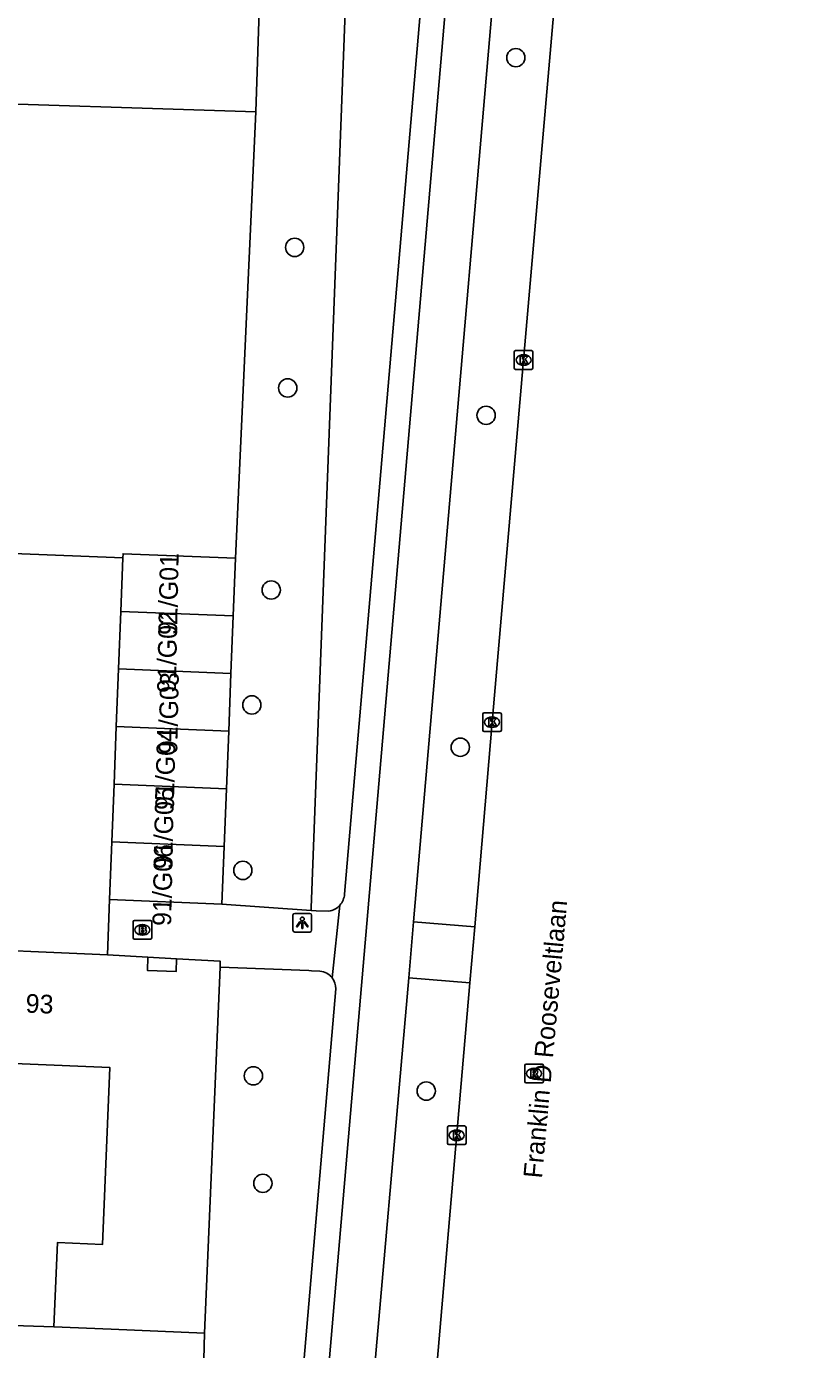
# Model space of a CAD drawing. Extents: x 160787 to 161428, y 386828 to 387483.
# Drawn here: x 161365.7 to 161407.5, y 386925.5 to 386996.4 of the extents above; entities that cross this region are included whole.
import ezdxf

# ---------------------------------------------------------------- set-up
doc = ezdxf.new("R2010")
doc.units = 0
for name, color, linetype in [('IMGEO_Boom', 7, 'Continuous'), ('IMGEO_Brandkraan', 7, 'Continuous'), ('IMGEO_Fietspad_gesloten', 7, 'Continuous'), ('IMGEO_Groenvoorziening', 7, 'Continuous'), ('IMGEO_Kolk', 7, 'Continuous'), ('IMGEO_Lichtpunt', 7, 'Continuous'), ('IMGEO_Openbare_ruimte_label', 7, 'Continuous'), ('IMGEO_Pand', 7, 'Continuous'), ('IMGEO_Pand_nummerreeks', 7, 'Continuous'), ('IMGEO_Rijbaan_lokaal_gesloten', 7, 'Continuous'), ('IMGEO_Rijbaan_lokaal_open', 7, 'Continuous'), ('IMGEO_Rioolput', 7, 'Continuous'), ('IMGEO_Voetpad_open', 7, 'Continuous')]:
    doc.layers.add(name, color=color, linetype=linetype)

msp = doc.modelspace()

# ---------------------------------------------------------------- linework, layer by layer
at = {"layer": 'IMGEO_Boom'}
for centre in [(161391.916, 386994.712), (161380.077, 386984.552), (161379.703, 386977.028), (161390.324, 386975.563), (161378.819, 386966.209), (161377.782, 386960.057), (161388.941, 386957.792), (161377.301, 386951.199), (161377.865, 386940.199), (161387.118, 386939.384), (161378.372, 386934.443)]:
    msp.add_circle(centre, 0.489, dxfattribs=at)
at = {"layer": 'IMGEO_Brandkraan'}
for p, q in [((161371.496, 386948.514), (161372.348, 386948.514)), ((161371.421, 386947.588), (161371.421, 386948.44)), ((161371.909, 386948.294), (161371.934, 386948.294)), ((161372.422, 386948.44), (161372.422, 386947.588)), ((161372.348, 386947.514), (161371.496, 386947.514)), ((161371.932, 386947.734), (161371.907, 386947.734))]:
    msp.add_line(p, q, dxfattribs=at)
for points in [[(161371.496, 386948.514), (161372.348, 386948.514)], [(161371.421, 386947.588), (161371.421, 386948.44)], [(161371.769, 386948.214), (161371.769, 386947.814), (161371.982, 386947.814)], [(161372, 386948.214), (161371.769, 386948.214)], [(161371.948, 386948.133), (161371.894, 386948.133), (161371.894, 386948.057)], [(161371.894, 386948.057), (161371.947, 386948.057)], [(161371.956, 386947.981), (161371.894, 386947.981), (161371.894, 386947.9)], [(161371.894, 386947.9), (161371.956, 386947.9)], [(161372.422, 386948.44), (161372.422, 386947.588)], [(161372.348, 386947.514), (161371.496, 386947.514)]]:
    msp.add_lwpolyline(points, dxfattribs=at)
for centre, radius, start, end in [((161371.498, 386948.438), 0.0765, 91.55205, 178.44795), ((161371.498, 386948.438), 0.0765, 91.55205, 178.44795), ((161372.346, 386948.438), 0.0765, 1.55205, 88.44795), ((161372.346, 386948.438), 0.0765, 1.55205, 88.44795), ((161371.949, 386948.095), 0.0379, 267.82845, 90.93552), ((161371.957, 386947.94), 0.0404, 269.87594, 90.50774), ((161371.988, 386948.065), 0.251, 268.66757, 293.53466), ((161372.004, 386948.069), 0.145, 59.4692, 91.53667), ((161372.029, 386948.116), 0.0922, 285.51372, 58.15012), ((161372.034, 386947.924), 0.105, 301.31148, 78.98903), ((161371.498, 386947.59), 0.0765, 181.55205, 268.44795), ((161371.498, 386947.59), 0.0765, 181.55205, 268.44795), ((161372.346, 386947.59), 0.0765, 271.55205, 358.44795), ((161372.346, 386947.59), 0.0765, 271.55205, 358.44795)]:
    msp.add_arc(centre, radius, start, end, dxfattribs=at)
for centre, major_axis, ratio, start_param, end_param in [((161371.908, 386948.014), (-0.387, 0.002), 0.722429, 4.712389, 7.853982), ((161371.933, 386948.014), (-0.39, 0.002), 0.717154, 1.570796, 4.712389)]:
    msp.add_ellipse(centre, major_axis=major_axis, ratio=ratio, start_param=start_param, end_param=end_param, dxfattribs=at)
at = {"layer": 'IMGEO_Fietspad_gesloten'}
for points in [[(161407.533, 387249.962), (161407.461, 387247.985), (161406.867, 387233.118), (161405.924, 387208.411), (161404.815, 387191.258), (161403.255, 387173.245), (161393.155, 387056.153), (161390.436, 387023.76), (161389.845, 387017.132), (161384.142, 386950.642), (161379.486, 386896.649), (161376.409, 386860.953), (161376.305, 386860.089), (161375.969, 386856.03)], [(161386.443, 386948.447), (161392.377, 387017.448)], [(161386.193, 386945.455), (161386.443, 386948.447)], [(161380.021, 386874.137), (161380.151, 386878.097), (161380.414, 386880.385), (161381.868, 386896.26), (161386.193, 386945.455)]]:
    msp.add_lwpolyline(points, dxfattribs=at)
at = {"layer": 'IMGEO_Groenvoorziening'}
for points in [[(161383.565, 387017.876), (161382.888, 387000), (161380.963, 386949.203), (161380.958, 386949.059)], [(161378.212, 386998.287), (161377.988, 386991.819)], [(161377.988, 386991.819), (161324.809, 386993.526)], [(161376.903, 386967.918), (161377.988, 386991.819)], [(161360.13, 386926.991), (161367.184, 386926.77)], [(161375.253, 386926.43), (161375.065, 386919.394)]]:
    msp.add_lwpolyline(points, dxfattribs=at)
at = {"layer": 'IMGEO_Kolk'}
for p, q in [((161391.83, 386978.098), (161391.83, 386978.95)), ((161391.905, 386979.024), (161392.757, 386979.024)), ((161392.831, 386978.95), (161392.831, 386978.098)), ((161392.341, 386978.244), (161392.316, 386978.244)), ((161392.318, 386978.804), (161392.343, 386978.804)), ((161392.757, 386978.024), (161391.905, 386978.024)), ((161390.14, 386958.706), (161390.14, 386959.558)), ((161390.215, 386959.632), (161391.067, 386959.632)), ((161390.628, 386959.412), (161390.653, 386959.412)), ((161391.141, 386959.558), (161391.141, 386958.706)), ((161391.067, 386958.632), (161390.215, 386958.632)), ((161390.651, 386958.852), (161390.626, 386958.852)), ((161388.25, 386936.59), (161388.25, 386937.442)), ((161388.325, 386937.516), (161389.177, 386937.516)), ((161388.738, 386937.296), (161388.763, 386937.296)), ((161389.251, 386937.442), (161389.251, 386936.59)), ((161389.177, 386936.516), (161388.325, 386936.516)), ((161388.761, 386936.736), (161388.736, 386936.736))]:
    msp.add_line(p, q, dxfattribs=at)
for points in [[(161391.83, 386978.098), (161391.83, 386978.95)], [(161391.905, 386979.024), (161392.757, 386979.024)], [(161392.831, 386978.95), (161392.831, 386978.098)], [(161392.151, 386978.724), (161392.274, 386978.724), (161392.274, 386978.573), (161392.404, 386978.724), (161392.568, 386978.724), (161392.422, 386978.573), (161392.575, 386978.324), (161392.423, 386978.324), (161392.338, 386978.488), (161392.274, 386978.421), (161392.274, 386978.324), (161392.151, 386978.324), (161392.151, 386978.724)], [(161392.757, 386978.024), (161391.905, 386978.024)], [(161390.14, 386958.706), (161390.14, 386959.558)], [(161390.215, 386959.632), (161391.067, 386959.632)], [(161390.461, 386959.332), (161390.584, 386959.332), (161390.584, 386959.181), (161390.714, 386959.332), (161390.878, 386959.332), (161390.732, 386959.181), (161390.885, 386958.932), (161390.733, 386958.932), (161390.648, 386959.096), (161390.584, 386959.029), (161390.584, 386958.932), (161390.461, 386958.932), (161390.461, 386959.332)], [(161391.141, 386959.558), (161391.141, 386958.706)], [(161391.067, 386958.632), (161390.215, 386958.632)], [(161388.25, 386936.59), (161388.25, 386937.442)], [(161388.325, 386937.516), (161389.177, 386937.516)], [(161388.571, 386937.216), (161388.694, 386937.216), (161388.694, 386937.065), (161388.824, 386937.216), (161388.988, 386937.216), (161388.842, 386937.065), (161388.995, 386936.816), (161388.843, 386936.816), (161388.758, 386936.98), (161388.694, 386936.913), (161388.694, 386936.816), (161388.571, 386936.816), (161388.571, 386937.216)], [(161389.251, 386937.442), (161389.251, 386936.59)], [(161389.177, 386936.516), (161388.325, 386936.516)]]:
    msp.add_lwpolyline(points, dxfattribs=at)
for centre, start, end in [((161391.907, 386978.948), 91.55205, 178.44795), ((161391.907, 386978.948), 91.55205, 178.44795), ((161392.755, 386978.948), 1.55205, 88.44795), ((161392.755, 386978.948), 1.55205, 88.44795), ((161391.907, 386978.1), 181.55205, 268.44795), ((161391.907, 386978.1), 181.55205, 268.44795), ((161392.755, 386978.1), 271.55205, 358.44795), ((161392.755, 386978.1), 271.55205, 358.44795), ((161390.217, 386959.556), 91.55205, 178.44795), ((161390.217, 386959.556), 91.55205, 178.44795), ((161391.065, 386959.556), 1.55205, 88.44795), ((161391.065, 386959.556), 1.55205, 88.44795), ((161390.217, 386958.708), 181.55205, 268.44795), ((161390.217, 386958.708), 181.55205, 268.44795), ((161391.065, 386958.708), 271.55205, 358.44795), ((161391.065, 386958.708), 271.55205, 358.44795), ((161388.327, 386937.44), 91.55205, 178.44795), ((161388.327, 386937.44), 91.55205, 178.44795), ((161389.175, 386937.44), 1.55205, 88.44795), ((161389.175, 386937.44), 1.55205, 88.44795), ((161388.327, 386936.592), 181.55205, 268.44795), ((161388.327, 386936.592), 181.55205, 268.44795), ((161389.175, 386936.592), 271.55205, 358.44795), ((161389.175, 386936.592), 271.55205, 358.44795)]:
    msp.add_arc(centre, 0.0765, start, end, dxfattribs=at)
for centre, major_axis, ratio, start_param, end_param in [((161392.317, 386978.524), (-0.387, 0.002), 0.722429, 4.712389, 7.853982), ((161392.342, 386978.524), (-0.39, 0.002), 0.717154, 1.570796, 4.712389), ((161390.627, 386959.132), (-0.387, 0.002), 0.722429, 4.712389, 7.853982), ((161390.652, 386959.132), (-0.39, 0.002), 0.717154, 1.570796, 4.712389), ((161388.737, 386937.016), (-0.387, 0.002), 0.722429, 4.712389, 7.853982), ((161388.762, 386937.016), (-0.39, 0.002), 0.717154, 1.570796, 4.712389)]:
    msp.add_ellipse(centre, major_axis=major_axis, ratio=ratio, start_param=start_param, end_param=end_param, dxfattribs=at)
at = {"layer": 'IMGEO_Lichtpunt'}
for p, q in [((161379.984, 386948.798), (161379.984, 386947.991)), ((161379.984, 386948.798), (161379.984, 386947.991)), ((161380.886, 386948.893), (161380.078, 386948.893)), ((161380.886, 386948.893), (161380.078, 386948.893)), ((161380.98, 386947.991), (161380.98, 386948.798)), ((161380.98, 386947.991), (161380.98, 386948.798)), ((161380.078, 386947.897), (161380.886, 386947.897)), ((161380.078, 386947.897), (161380.886, 386947.897))]:
    msp.add_line(p, q, dxfattribs=at)
for points in [[(161380.358, 386948.462), (161380.397, 386948.434), (161380.209, 386948.172), (161380.171, 386948.199), (161380.358, 386948.462)], [(161380.46, 386948.414), (161380.507, 386948.414), (161380.507, 386948.092), (161380.46, 386948.092), (161380.46, 386948.414)], [(161380.57, 386948.434), (161380.608, 386948.461), (161380.795, 386948.199), (161380.756, 386948.171), (161380.57, 386948.434)]]:
    msp.add_lwpolyline(points, dxfattribs=at)
msp.add_circle((161380.483, 386948.596), 0.0994, dxfattribs=at)
for centre, start, end in [((161380.078, 386948.798), 90, 180), ((161380.078, 386948.798), 90, 180), ((161380.886, 386948.798), 0, 90), ((161380.886, 386948.798), 0, 90), ((161380.078, 386947.991), 180, 270), ((161380.078, 386947.991), 180, 270), ((161380.886, 386947.991), 270, 0), ((161380.886, 386947.991), 270, 360)]:
    msp.add_arc(centre, 0.0946, start, end, dxfattribs=at)
at = {"layer": 'IMGEO_Pand'}
for points in [[(161370.765, 386965.067), (161370.877, 386967.928)], [(161370.877, 386967.928), (161370.886, 386968.153), (161376.903, 386967.918)], [(161376.903, 386967.918), (161376.782, 386964.832)], [(161370.644, 386961.981), (161370.765, 386965.067)], [(161376.782, 386964.832), (161370.765, 386965.067)], [(161376.782, 386964.832), (161376.661, 386961.745)], [(161370.523, 386958.894), (161370.644, 386961.981)], [(161376.661, 386961.745), (161370.644, 386961.981)], [(161376.661, 386961.745), (161376.541, 386958.659)], [(161370.403, 386955.808), (161370.523, 386958.894)], [(161370.523, 386958.894), (161376.541, 386958.659)], [(161376.541, 386958.659), (161376.42, 386955.572)], [(161370.282, 386952.721), (161370.403, 386955.808)], [(161370.403, 386955.808), (161376.42, 386955.572)], [(161376.42, 386955.572), (161376.299, 386952.486)], [(161370.161, 386949.634), (161370.282, 386952.721)], [(161370.282, 386952.721), (161376.299, 386952.486)], [(161376.299, 386952.486), (161376.178, 386949.399)], [(161376.178, 386949.399), (161370.161, 386949.634)], [(161361.02, 386947.066), (161360.81, 386942.071), (161360.767, 386941.044), (161370.177, 386940.648), (161369.778, 386931.17), (161367.373, 386931.271), (161367.184, 386926.77)], [(161361.02, 386947.066), (161370.046, 386946.686)], [(161370.046, 386946.686), (161372.217, 386946.56)], [(161373.755, 386946.471), (161373.726, 386945.782), (161372.187, 386945.846), (161372.217, 386946.56)], [(161373.755, 386946.471), (161376.09, 386946.336), (161376.077, 386946.026)], [(161376.077, 386946.026), (161375.253, 386926.43)], [(161367.184, 386926.77), (161370.258, 386926.64), (161375.253, 386926.43)]]:
    msp.add_lwpolyline(points, dxfattribs=at)
at = {"layer": 'IMGEO_Rijbaan_lokaal_gesloten'}
for points in [[(161395.645, 387017.152), (161393.997, 386997.829), (161392.331, 386978.524), (161390.641, 386959.132), (161389.725, 386948.174)], [(161389.725, 386948.174), (161389.46, 386945.188)], [(161389.46, 386945.188), (161387.076, 386917.62), (161385.411, 386898.291), (161383.44, 386875.95), (161383.252, 386873.773)]]:
    msp.add_lwpolyline(points, dxfattribs=at)
at = {"layer": 'IMGEO_Rijbaan_lokaal_open'}
for points in [[(161329.654, 386962.268), (161329.879, 386969.558), (161370.877, 386967.928)], [(161370.161, 386949.634), (161370.046, 386946.686)]]:
    msp.add_lwpolyline(points, dxfattribs=at)
at = {"layer": 'IMGEO_Rioolput'}
for p, q in [((161392.39, 386939.896), (161392.39, 386940.748)), ((161392.465, 386940.822), (161393.317, 386940.822)), ((161393.391, 386940.748), (161393.391, 386939.896)), ((161392.901, 386940.042), (161392.876, 386940.042)), ((161392.878, 386940.602), (161392.903, 386940.602)), ((161393.317, 386939.822), (161392.465, 386939.822))]:
    msp.add_line(p, q, dxfattribs=at)
for points in [[(161392.39, 386939.896), (161392.39, 386940.748)], [(161392.465, 386940.822), (161393.317, 386940.822)], [(161393.391, 386940.748), (161393.391, 386939.896)], [(161392.979, 386940.52), (161392.727, 386940.522), (161392.727, 386940.122)], [(161392.727, 386940.122), (161392.851, 386940.122), (161392.851, 386940.284), (161392.862, 386940.284)], [(161392.905, 386940.441), (161392.851, 386940.441), (161392.851, 386940.36)], [(161392.851, 386940.36), (161392.903, 386940.36)], [(161392.909, 386940.255), (161392.98, 386940.122), (161393.12, 386940.122), (161393.055, 386940.248)], [(161393.317, 386939.822), (161392.465, 386939.822)]]:
    msp.add_lwpolyline(points, dxfattribs=at)
for centre, radius, start, end in [((161392.467, 386940.746), 0.0765, 91.55205, 178.44795), ((161392.467, 386940.746), 0.0765, 91.55205, 178.44795), ((161393.315, 386940.746), 0.0765, 1.55205, 88.44795), ((161393.315, 386940.746), 0.0765, 1.55205, 88.44795), ((161392.861, 386940.231), 0.0533, 26.02933, 88.69889), ((161392.887, 386940.549), 0.19, 274.7715, 282.96867), ((161392.911, 386940.345), 0.0964, 77.00612, 93.18647), ((161392.925, 386940.402), 0.0378, 276.66336, 79.67722), ((161392.978, 386940.41), 0.109, 350.36119, 89.41601), ((161392.976, 386940.41), 0.112, 277.58423, 350.98172), ((161392.96, 386940.195), 0.108, 29.51342, 73.79051), ((161392.467, 386939.898), 0.0765, 181.55205, 268.44795), ((161392.467, 386939.898), 0.0765, 181.55205, 268.44795), ((161393.315, 386939.898), 0.0765, 271.55205, 358.44795), ((161393.315, 386939.898), 0.0765, 271.55205, 358.44795)]:
    msp.add_arc(centre, radius, start, end, dxfattribs=at)
for centre, major_axis, ratio, start_param, end_param in [((161392.877, 386940.322), (-0.387, 0.002), 0.722429, 4.712389, 7.853982), ((161392.902, 386940.322), (-0.39, 0.002), 0.717154, 1.570796, 4.712389)]:
    msp.add_ellipse(centre, major_axis=major_axis, ratio=ratio, start_param=start_param, end_param=end_param, dxfattribs=at)
at = {"layer": 'IMGEO_Voetpad_open'}
for points in [[(161382.742, 386949.926), (161388.492, 387016.802)], [(161380.958, 386949.059), (161376.178, 386949.399)], [(161382.082, 386945.443), (161382.498, 386949.34)], [(161380.958, 386949.059), (161381.225, 386949.04), (161381.89, 386949.011)], [(161386.443, 386948.447), (161389.725, 386948.174)], [(161372.217, 386946.56), (161373.755, 386946.471)], [(161376.077, 386946.026), (161380.826, 386945.831), (161380.968, 386945.825), (161381.429, 386945.806)], [(161389.46, 386945.188), (161386.193, 386945.455)], [(161382.281, 386944.856), (161378.179, 386896.984), (161376.451, 386877.078), (161373.262, 386877.418)]]:
    msp.add_lwpolyline(points, dxfattribs=at)
for centre, radius, start, end in [((161381.75, 386949.995), 0.995, 318.78478, 356.00326), ((161381.752, 386949.993), 0.991, 278.01319, 318.82408), ((161381.33, 386944.859), 0.952, 37.82967, 84.03133), ((161381.335, 386944.862), 0.946, 359.61354, 37.84101)]:
    msp.add_arc(centre, radius, start, end, dxfattribs=at)

# ---------------------------------------------------------------- texts
at = {"layer": 'IMGEO_Openbare_ruimte_label'}
msp.add_text('Franklin D Rooseveltlaan', height=1, rotation=84.77964, dxfattribs=at).set_placement((161393.312, 386934.687))
at = {"layer": 'IMGEO_Pand_nummerreeks'}
for s, rotation, p in [('91/G01', 88.80235, (161373.774, 386963.793)), ('91/G02', 88.80235, (161373.709, 386960.686)), ('91/G03', 88.80235, (161373.783, 386957.413)), ('91/G04', 88.80235, (161373.611, 386954.422)), ('91/G05', 88.80235, (161373.522, 386951.258)), ('91/G06', 88.80235, (161373.459, 386948.217)), ('93', 357.59358, (161365.655, 386943.588))]:
    msp.add_text(s, height=1, rotation=rotation, dxfattribs=at).set_placement(p)

doc.saveas('drawing.dxf')
